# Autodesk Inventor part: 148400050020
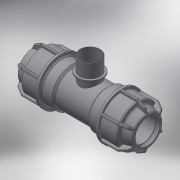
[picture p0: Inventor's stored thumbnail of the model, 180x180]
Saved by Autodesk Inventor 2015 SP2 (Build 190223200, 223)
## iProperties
Created: 2017-08
Part Number: 148400050020
Material: Generic
Description: PLASSON L.14 TEE MALE ADAPTOR (SILVER) 50-2"-50
Document SubType Name: Modeling
Designer: KIM
Density: 1 g/cm^3
Appearance: Default
Author: KIM
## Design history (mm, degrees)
derived "148400.ipt"
feature "Solid1::148400.ipt"
feature "Solid2::148400.ipt"
tag "TaggingFeature1"
body "Solid1"
body "Solid2"
other parameters: "d2" = 72, "d4" = 15 deg, "d5" = 47.52, "d6" = 15.6816, "d10" = 92, "d16" = 51, "d17" = 3.6, "d24" = 3.6, "d25" = 82.8, "d26" = 69, "d27" = 3.6, "d28" = 135 deg, "d29" = 2.16, "d31" = 2.5, "d46" = 150 deg, "d49" = 4.6, "d50" = 0, "d58" = 1.5, "d61" = 360 deg, "d63" = 45, "d64" = 103.5, "d80" = 72, "d81" = 4, "d84" = 3.6, "d94" = 77, "d96" = 59.614, "d108" = 1.5, "d111" = 0, "d113" = 45, "d114" = 71.5368, "d115" = 26, "d116" = 2.6, "d117" = 53.6526, "R_" = 59.614, "E_" = 92, "H_" = 207, "l_" = 72, "l_2" = 26, "A_" = 77
